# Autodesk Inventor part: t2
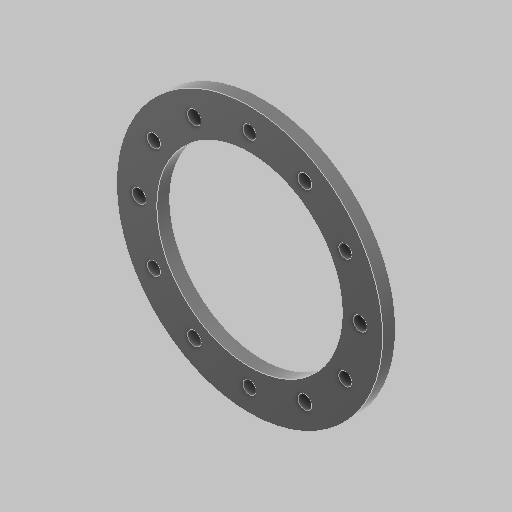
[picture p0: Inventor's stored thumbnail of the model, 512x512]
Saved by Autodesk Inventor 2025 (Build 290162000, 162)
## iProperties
Created: 2025-01
Part Number: t2
Material: Thermoplastic Resin
Document SubType Name: Modeling
Designer: dansp
Density: 1.28 g/cm^3
Appearance: Smooth - Black
Mass: 13.2627 g
Surface Area: 75.5829 cm^2
Volume: 10.3615 cm^3
Author: dansp
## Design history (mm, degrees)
sketch "Sketch1"
  geometry: L1 (0, 57.75)-(0, -57.75) reference; L2 (-57.75, 0)-(57.75, 0) reference; C1 r 41.25 at (0, 0); C2 r 28.75 at (0, 0); 1 further point
  constraints: 2 centre point, 2 coincident
  dimensions: "d0" = 82.5 diameter of C1; "d1" = 12.5 radial gap between concentric circles of C1 C2
extrude "Extrusion1" new body sketch "Sketch1" distance "d2" = 4; taper "d3" = 0 deg
sketch "Sketch2"
  geometry: L1 (0, 59.5)-(0, -59.5) reference; 6 further points
  constraints: 3 point on line, 2 vertical alignment, 2 other
  dimensions: "d4" = 7 distance of point (0, 41.25) point (0, 34.25)
hole "Hole1" sketch "Sketch2" at (0, 34.25) diameter "d5" = 4; stored, may be unused: countersink angle "d9" = 90 deg, drill point angle "d11" = 118 deg; dims "d6" = 12, "d7" = 4, "d8" = 2, "d10" = 8
pattern_circular "Circular Pattern2" dims angle "d18" = 360 deg
thread "Thread2" dims "d20" = 5, "d21" = 0
thread "Thread3" dims "d22" = 5, "d23" = 0
thread "Thread4" dims "d24" = 5, "d25" = 0
thread "Thread5" dims "d26" = 5, "d27" = 0
thread "Thread6" dims "d28" = 5, "d29" = 0
thread "Thread7" dims "d30" = 5, "d31" = 0
sketch "Sketch17"
  geometry: L1 (0, 0)-(-17.125, 29.661); L2 (0, -57.75)-(0, 57.75) reference; L3 (0, 0)-(20.74, -35.923); C1 r 2 at (-29.661, 17.125) reference; C2 r 2.1 at (-17.125, 29.661); C3 r 2.1 at (17.125, -29.661); A1 r 34.25 centre (0, 0) between (-29.661, 17.125) and (-17.125, 29.661); 1 further point
  constraints: 4 end point, 3 centre point, 3 point on circle, 1 coincident, 1 collinear, 1 point on line
  dimensions: "d148" = 4.2 diameter of C2; "d150" = 30 deg angle of L2 L1; "d151" = 4.2 diameter of C3 (= d148)
extrude "Extrusion3" cut sketch "Sketch17" extent not by distance; stored distance "d152" = 0; taper "d153" = 0 deg
pattern_circular "Circular Pattern3" dims angle "d155" = 360 deg
body "Solid1"
node "Projected Loop1"
other parameters: "d39" = 55 deg [user parameter], "Sketch3_Pitch" = 0.7 [user parameter], "d57" = 55 deg [user parameter], "Sketch5_Pitch" = 0.7 [user parameter], "d75" = 55 deg [user parameter], "Sketch7_Pitch" = 0.7 [user parameter], "d93" = 55 deg [user parameter], "Sketch9_Pitch" = 0.7 [user parameter], "d111" = 55 deg [user parameter], "Sketch11_Pitch" = 0.7 [user parameter], "d129" = 55 deg [user parameter], "Sketch13_Pitch" = 0.7 [user parameter]
